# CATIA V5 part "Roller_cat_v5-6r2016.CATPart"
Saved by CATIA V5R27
Part number: Roller
Bounding box of the stored display mesh (mm): x 0 to 20, y -10 to 10, z -10 to 10
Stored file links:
  E:\_Deepak\2017_Deepak\CATIA\Resources\Tutorial Files\Tutorials\c16_catia_v5_6r2016_tut\Bearing\Roller_cat_v5-6r2016.CATPart
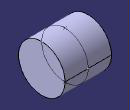
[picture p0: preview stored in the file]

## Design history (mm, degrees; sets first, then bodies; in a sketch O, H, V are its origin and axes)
Body1 (main body)
  Sketch1 on yz-plane, origin (0, 0, 0), H (0, 1, 0), V (0, 0, 1)
    circle A1 centre (0, 0) radius 10
    radius A1 = 10
  Pad1: profile Sketch1, direction (1, 0, 0), length 20
  Plane1: type Offset, RefPlane end face of Pad1, Offset -10, reversed
  Sketch2 on Plane1, origin (10, 0, 0), H (0, -1, 0), V (0, 0, 1)
    projected circle E1 centre (0, 0) radius 10 from edge [face of Pad1 from Sketch1.A1 | end face of Pad1]
    point P1 (0, -10)
    point P2 (0, 10)
    coincidence: P1 E1, P1 V, P2 V, E1 P2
